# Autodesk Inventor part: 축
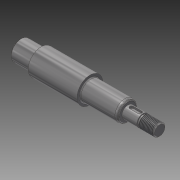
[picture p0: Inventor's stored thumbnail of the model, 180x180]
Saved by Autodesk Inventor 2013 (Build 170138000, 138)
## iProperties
Created: 2015-12
Part Number: 축
Material: 강철, 연강
Document SubType Name: Modeling
Designer: mdu
Density: 7.86 g/cm^3
CustomPartVersion: 1
Author: mdu
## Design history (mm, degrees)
sketch "스케치5"
  geometry: L1 (0, 0)-(140, 0); L2 (0, 0)-(140, 0); L3 (140, 0)-(140, 6); L4 (108, 6)-(108, 8.85); L5 (106.008, 10)-(70, 10); L6 (70, 10)-(70, 13); L7 (70, 13)-(21, 13); L8 (21, 13)-(21, 10); L9 (21, 10)-(0, 10); L10 (0, 10)-(0, 0); L11 (123, 6)-(123, 5); L12 (123, 5)-(125, 5); L13 (125, 5)-(125, 6); L14 (140, 6)-(125, 6); L15 (123, 6)-(108, 6); L16 (108, 8.85)-(106.008, 10)
  constraints: 33 end point, 12 perpendicular, 9 parallel, 1 collinear, 1 horizontal
  dimensions: "d43" = 20 diameter of L9 L1; "d44" = 26 diameter of L7 L1; "d45" = 20 diameter of L5 L2; "d47" = 49 distance of L6.end L7.end; "d48" = 32 distance between parallel lines of L3 L4; "d50" = 21 distance of L8.end L9.end; "d52" = 12 diameter of L14 L1; "d53" = 15 distance between parallel lines of L3 L13; "d54" = 2 distance of L11.end L12.end; "d55" = 1 distance between parallel lines of L14 L12; "d64" = 140 distance of L1.start L1.end; "d65" = 30 deg angle of L5 L16; "d66" = 17.7 diameter of L4.end L1
revolve "회전4" sketch "스케치5" stored, may be unused: angle "d51" = 90 deg
feature "스레드6" dims "d56" = 10, "d57" = 0
chamfer "모따기6" distance "d32" = 1; stored, may be unused: second distance "d33" = 0.4, angle "d34" = 45 deg
chamfer "모따기5" distance "d27" = 1; stored, may be unused: second distance "d28" = 0.125, angle "d29" = 45 deg
fillet "모깎기1" dims "d17" = 1
node "작업 평면1"
sketch "스케치6"
  geometry: L1 (-3.5, 2)-(4.5, 2); L2 (4.5, -2)-(-3.5, -2); L3 (-7.5, -8.85)-(-7.5, 8.85) reference; A1 r 2 centre (4.5, 0) between (4.5, -2) and (4.5, 2); A2 r 2 centre (-3.5, 0) between (-3.5, 2) and (-3.5, -2); 1 further point
  constraints: 4 end point, 4 point on circle, 4 tangent, 2 centre point, 1 horizontal, 1 horizontal alignment, 1 parallel
  dimensions: "d60" = 12 dimension on A1 A2; "d61" = 4 distance between parallel lines of L2 L1; "d67" = 2 distance edge to line of A2 L3
extrude "돌출1" cut sketch "스케치6" distance "d62" = 2.3; taper "d63" = 0 deg
fillet "모깎기3" dims "d68" = 1, "d69" = 4
node "솔리드1"
node "솔리드2"
other parameters: "d46" = 12
